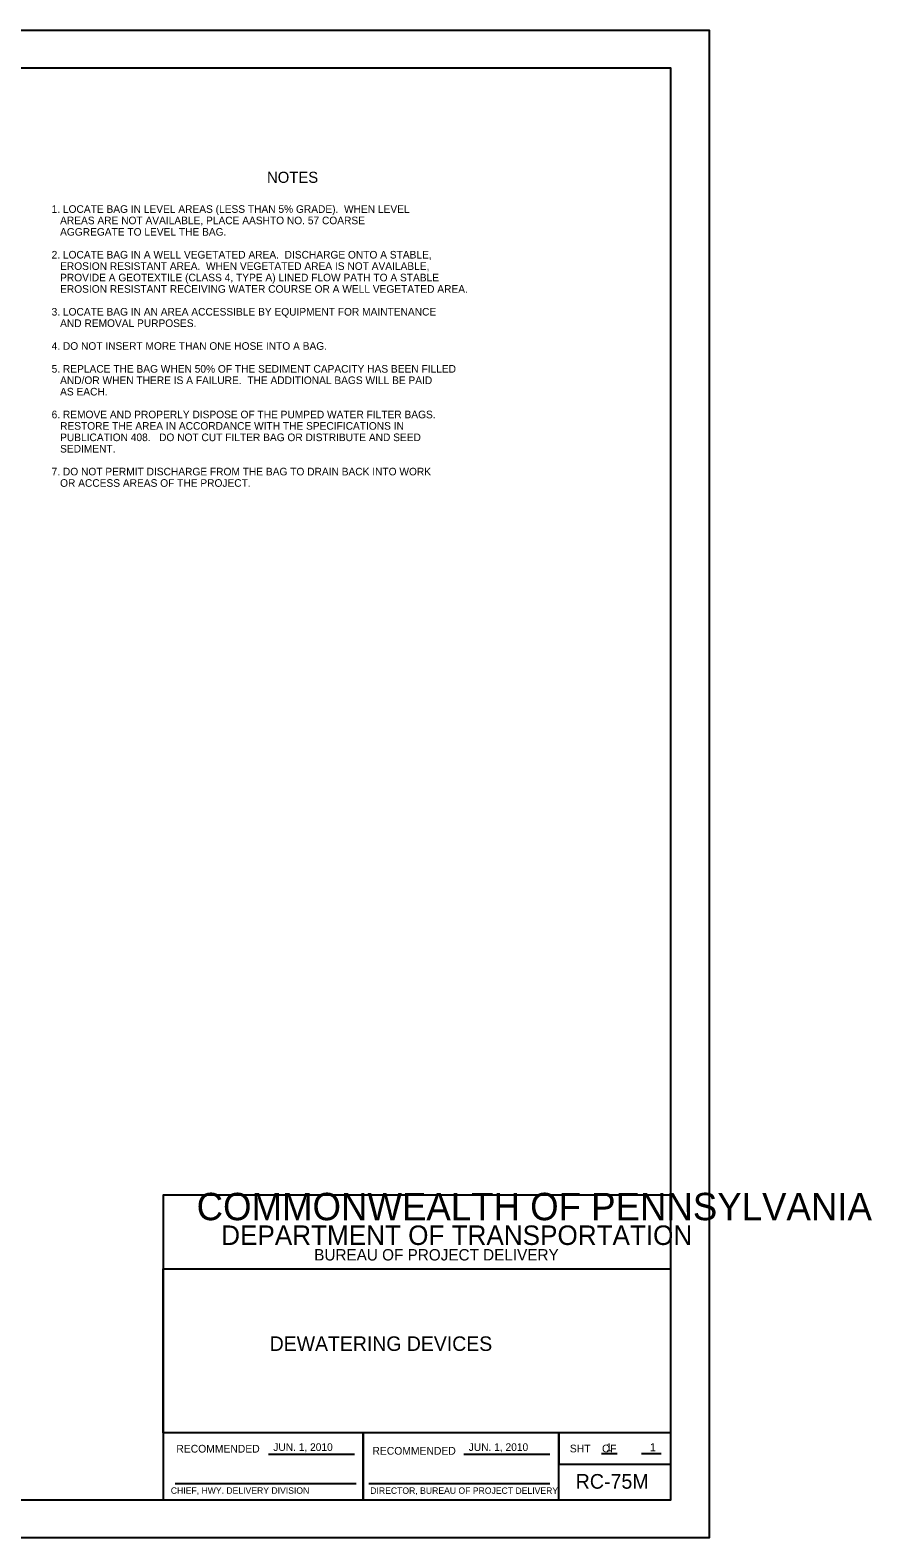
# Model space of a CAD drawing. Extents: x 636462 to 637367, y 299944 to 300538.
# Drawn here: x 637035 to 637367, y 299944 to 300538 of the extents above; entities that cross this region are included whole.
import ezdxf

# ---------------------------------------------------------------- set-up
doc = ezdxf.new("R2010")
doc.units = 0
for name, color, linetype in [('1', 7, 'Continuous'), ('Default', 7, 'Continuous'), ('PLT-BNDY', 7, 'Continuous')]:
    doc.layers.add(name, color=color, linetype=linetype)

msp = doc.modelspace()

# ---------------------------------------------------------------- linework, layer by layer
at = {"layer": '1'}
for p, q in [((637129.38, 299977.44), (637163.27, 299977.44)), ((637206.38, 299977.44), (637240.25, 299977.44)), ((637260.54, 299977.66), (637266.68, 299977.66)), ((637276.35, 299977.66), (637283.99, 299977.66)), ((637092.68, 299965.87), (637163.93, 299965.87)), ((637168.85, 299965.87), (637240.19, 299965.87))]:
    msp.add_line(p, q, dxfattribs=at)
msp.add_lwpolyline([(637287.91, 299959.45), (637287.91, 300523.45), (636501.91, 300523.45), (636501.91, 299959.45), (637287.91, 299959.45), (637287.91, 299985.81), (637087.91, 299985.81), (637087.91, 300050.49), (637287.91, 300050.49), (637287.91, 300079.45), (637087.91, 300079.45), (637087.91, 299959.45), (637166.72, 299959.45), (637166.72, 299985.81), (637166.72, 299959.45), (637243.72, 299959.45), (637243.72, 299985.81), (637243.72, 299973.49), (637287.91, 299973.49)], dxfattribs=at)
at = {"layer": 'PLT-BNDY'}
msp.add_lwpolyline([(636461.91, 300538.45), (637302.91, 300538.45), (637302.91, 299944.45), (636461.91, 299944.45)], close=True, dxfattribs=at)

# ---------------------------------------------------------------- texts
at = {"layer": '1'}
for s, height, p in [('COMMONWEALTH OF PENNSYLVANIA', 10.7834, (637101.07, 300069.59)), ('DEPARTMENT OF TRANSPORTATION', 7.6843, (637110.75, 300059.84)), ('BUREAU OF PROJECT DELIVERY', 4.5, (637147.39, 300053.72)), ('RECOMMENDED', 3.048, (637093.08, 299978.04)), ('APPROVED', 0.0192, (637130.94, 299977.38)), ('APPROVED', 0.0192, (637130.94, 299977.38)), ('APPROVED', 0.0192, (637130.94, 299977.38)), ('APPROVED', 0.0192, (637130.94, 299977.38)), ('JUN. 1, 2010', 3, (637131.26, 299978.69)), ('RECOMMENDED', 3.048, (637170.32, 299977.21)), ('JUN. 1, 2010', 3, (637208.26, 299978.69)), ('SHT    OF', 3.048, (637248.08, 299978.12)), ('1', 3.13, (637262.41, 299978.54)), ('1', 3.13, (637279.64, 299978.59)), ('CHIEF, HWY. DELIVERY DIVISION', 2.54, (637090.9, 299961.81)), ('DIRECTOR, BUREAU OF PROJECT DELIVERY', 2.54, (637169.48, 299961.78))]:
    msp.add_text(s, height=height, dxfattribs=at).set_placement(p)
at = {"layer": 'Default'}
for s, height, p in [('NOTES', 4.372, (637128.8, 300478.29)), ('1. LOCATE BAG IN LEVEL AREAS (LESS THAN 5% GRADE).  WHEN LEVEL', 2.998, (637043.95, 300466.47)), ('   AREAS ARE NOT AVAILABLE, PLACE AASHTO NO. 57 COARSE', 2.998, (637043.95, 300461.98)), ('   AGGREGATE TO LEVEL THE BAG.', 2.998, (637043.95, 300457.48)), ('2. LOCATE BAG IN A WELL VEGETATED AREA.  DISCHARGE ONTO A STABLE, ', 2.998, (637043.95, 300448.48)), ('   EROSION RESISTANT AREA.  WHEN VEGETATED AREA IS NOT AVAILABLE,', 2.998, (637043.95, 300443.99)), ('   PROVIDE A GEOTEXTILE (CLASS 4, TYPE A) LINED FLOW PATH TO A STABLE', 2.998, (637043.95, 300439.49)), ('   EROSION RESISTANT RECEIVING WATER COURSE OR A WELL VEGETATED AREA.', 2.998, (637043.95, 300434.99)), ('3. LOCATE BAG IN AN AREA ACCESSIBLE BY EQUIPMENT FOR MAINTENANCE', 2.998, (637043.95, 300426)), ('   AND REMOVAL PURPOSES.', 2.998, (637043.95, 300421.5)), ('4. DO NOT INSERT MORE THAN ONE HOSE INTO A BAG.', 2.998, (637043.95, 300412.51)), ('5. REPLACE THE BAG WHEN 50% OF THE SEDIMENT CAPACITY HAS BEEN FILLED', 2.998, (637043.95, 300403.51)), ('   AND/OR WHEN THERE IS A FAILURE.  THE ADDITIONAL BAGS WILL BE PAID', 2.998, (637043.95, 300399.02)), ('   AS EACH.', 2.998, (637043.95, 300394.52)), ('6. REMOVE AND PROPERLY DISPOSE OF THE PUMPED WATER FILTER BAGS.', 2.998, (637043.95, 300385.53)), ('   RESTORE THE AREA IN ACCORDANCE WITH THE SPECIFICATIONS IN ', 2.998, (637043.95, 300381.03)), ('   SEDIMENT.', 2.998, (637043.95, 300372.03)), ('   PUBLICATION 408.   DO NOT CUT FILTER BAG OR DISTRIBUTE AND SEED', 2.998, (637043.95, 300376.53)), ('7. DO NOT PERMIT DISCHARGE FROM THE BAG TO DRAIN BACK INTO WORK', 2.998, (637043.95, 300363.04)), ('   OR ACCESS AREAS OF THE PROJECT.', 2.998, (637043.95, 300358.54)), ('DEWATERING DEVICES', 5.7257, (637129.86, 300018.1)), ('RC-75M', 5.779, (637250.37, 299963.81))]:
    msp.add_text(s, height=height, dxfattribs=at).set_placement(p)

doc.saveas('drawing.dxf')
